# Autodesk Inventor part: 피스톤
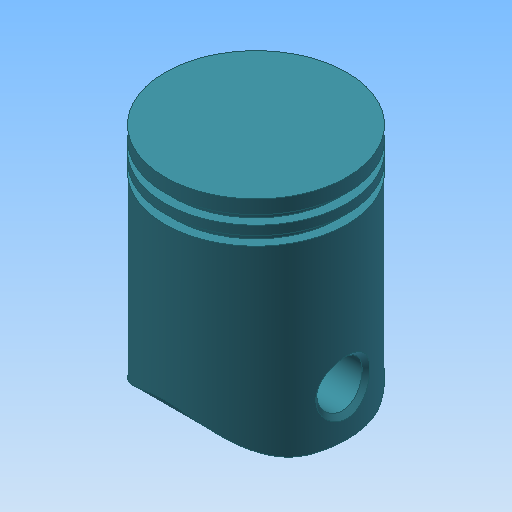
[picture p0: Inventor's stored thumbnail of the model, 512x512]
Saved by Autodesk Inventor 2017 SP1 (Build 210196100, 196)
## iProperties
Created: 2017-05
Part Number: 피스톤
Material: 알루미늄 6061
Document SubType Name: Modeling
Designer: mduedu
Density: 2.71 g/cm^3
Mass: 87.7002 g
Surface Area: 150.485 cm^2
Volume: 32.3617 cm^3
Appearance: 커뎃 파란색
Author: mduedu
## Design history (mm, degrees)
sketch "스케치1"
  geometry: L1 (0, 0)-(20, 0); L2 (20, -50)-(15, -50); L3 (15, -50)-(15, -5); L4 (15, -5)-(0, -5); L5 (0, -5)-(0, 0); L6 (20, -3)-(18, -3); L7 (18, -3)-(18, -5); L8 (18, -5)-(20, -5); L9 (20, -7)-(18, -7); L10 (18, -7)-(18, -9); L11 (18, -9)-(20, -9); L12 (20, 0)-(20, -3); L13 (20, -5)-(20, -7); L14 (20, -9)-(20, -50); L15 (0, -60)-(0, 10) reference
  constraints: 28 end point, 10 parallel, 5 perpendicular, 4 collinear, 3 horizontal
  dimensions: "d0" = 20 distance of L1.start L1.end; "d1" = 2 distance of L6.start L6.end; "d2" = 2 distance of L6.end L7.end; "d3" = 2 distance of L8.end L9.start; "d4" = 3 distance of L1.end L6.start; "d5" = 5 distance of L2.start L2.end; "d6" = 50 distance between parallel lines of L1 L2; "d7" = 5 distance of L4.end L1.start
revolve "회전1" sketch "스케치1" stored, may be unused: angle "d8" = 90 deg
fillet "모깎기1" dims "d9" = 1
sketch "스케치2"
  geometry: L1 (-50, 15)-(-50, -15) reference; C1 r 10 at (-40, 0); 1 further point
  constraints: 1 centre point, 1 horizontal alignment
  dimensions: "d10" = 20 diameter of C1; "d11" = 10 distance from line of C1.centre L1
extrude "돌출1" join sketch "스케치2" stored distance "d12" = 10; taper "d13" = 0 deg
sketch "스케치3"
  geometry: L1 (0, -20)-(-3, -20) reference; L2 (-3, -20)-(-3, -18) reference; L3 (-3, -18)-(-5, -18) reference; L4 (-5, -18)-(-5, -20) reference; L5 (-5, -20)-(-7, -20) reference; L6 (-7, -20)-(-7, -18) reference; L7 (-7, -18)-(-9, -18) reference; L8 (-9, -18)-(-9, -20) reference; L9 (-9, -20)-(-50, -20) reference; L10 (-50, -20)-(-50, -15) reference; L11 (-50, -15)-(-6, -15) reference; L12 (-5, -14)-(-5, 14) reference; L13 (-6, 15)-(-50, 15) reference; L14 (-50, 15)-(-50, 20) reference; L15 (-50, 20)-(-9, 20) reference; L16 (-9, 20)-(-9, 18) reference; L17 (-9, 18)-(-7, 18) reference; L18 (-7, 18)-(-7, 20) reference; L19 (-7, 20)-(-5, 20) reference; L20 (-5, 20)-(-5, 18) reference; L21 (-5, 18)-(-3, 18) reference; L22 (-3, 18)-(-3, 20) reference; L23 (-3, 20)-(0, 20) reference; L24 (0, 20)-(0, -20) reference; C1 r 10 at (-40, 0) reference; C2 r 5 at (-40, 0); A1 r 1 centre (-6, -14) between (-6, -15) and (-5, -14) reference; A2 r 1 centre (-6, 14) between (-5, 14) and (-6, 15) reference; 1 further point
  constraints: 1 centre point, 1 coincident
  dimensions: "d15" = 10 diameter of C2
extrude "돌출2" cut sketch "스케치3" stored distance "d16" = 10; taper "d17" = 0 deg
sketch "스케치4"
  geometry: L1 (15, -50)-(-15, -50) reference; L2 (-15, -50)-(-20, -50) reference; L3 (-20, -50)-(-20, -45) reference; L4 (20, -45)-(20, -50) reference; L5 (20, -50)-(15, -50) reference; L6 (-15, -30)-(15, -30) reference; L7 (15, -30)-(15, -6) reference; L8 (14, -5)-(-14, -5) reference; L9 (-15, -6)-(-15, -30) reference; L10 (-20, -3)-(-20, 0) reference; L11 (-20, 0)-(20, 0) reference; L12 (20, 0)-(20, -3) reference; L13 (20, -3)-(18, -3) reference; L14 (18, -3)-(18, -5) reference; L15 (18, -5)-(20, -5) reference; L16 (20, -5)-(20, -7) reference; L17 (20, -7)-(18, -7) reference; L18 (18, -7)-(18, -9) reference; L19 (18, -9)-(20, -9) reference; L20 (-20, -9)-(-18, -9) reference; L21 (-18, -9)-(-18, -7) reference; L22 (-18, -7)-(-20, -7) reference; L23 (-20, -7)-(-20, -5) reference; L24 (-20, -5)-(-18, -5) reference; L25 (-18, -5)-(-18, -3) reference; L26 (-18, -3)-(-20, -3) reference; L27 (0, 0)-(0, -50); L28 (-5.698, -50)-(-5, -30); L29 (5.698, -50)-(5, -30); L30 (-5, -30)-(5, -30); L31 (-5.698, -50)-(5.698, -50); L32 (-20, -45)-(20, -45) reference; L33 (20, -9)-(20, -35) reference; L34 (20, -35)-(-20, -35) reference; L35 (-20, -35)-(-20, -9) reference; A1 r 1 centre (14, -6) between (15, -6) and (14, -5) reference; A2 r 1 centre (-14, -6) between (-14, -5) and (-15, -6) reference
  constraints: 10 end point, 2 point on line, 2 symmetric about line, 1 midpoint, 1 parallel, 1 perpendicular
  dimensions: "d18" = 2 deg angle of L27 L28; "d19" = 5 distance from line of L27 L28.end
extrude "돌출3" cut sketch "스케치4" stored distance "d20" = 20; taper "d21" = 0 deg
chamfer "모따기1" distance "d22" = 1; stored, may be unused: second distance "d23" = 2, angle "d24" = 45 deg
sketch "스케치5"
  geometry: L1 (-50, 0)-(-50, -15) reference; L2 (-50, 15)-(-50, 0) reference; L3 (-9, 20)-(-50, 20) reference; L4 (-50, 20)-(-50, -20) reference; L5 (-9, -20)-(-50, -20) reference; L6 (-42.483, -20)-(-50, -20); L7 (-50, -20)-(-50, -7); L8 (-42.483, 20)-(-50, 20); L9 (-50, 20)-(-50, 7); A1 r 15 centre (-35, 7) between (-42.483, 20) and (-50, 7); A2 r 15 centre (-35, -7) between (-42.483, -20) and (-50, -7); 1 further point
  constraints: 8 end point, 4 point on circle, 4 point on line, 2 centre point, 2 tangent, 1 collinear, 1 equal radius, 1 perpendicular
  dimensions: "d25" = 30 diameter of A1; "d26" = 7 vertical distance of A2.centre point (0, 0); "d27" = 7 vertical distance of point (0, 0) A1.centre (= d26)
extrude "돌출4" cut sketch "스케치5" stored distance "d28" = 20; taper "d29" = 0 deg
node "솔리드1"
node "절단 모서리 투영1"
node "절단 모서리 투영2"
